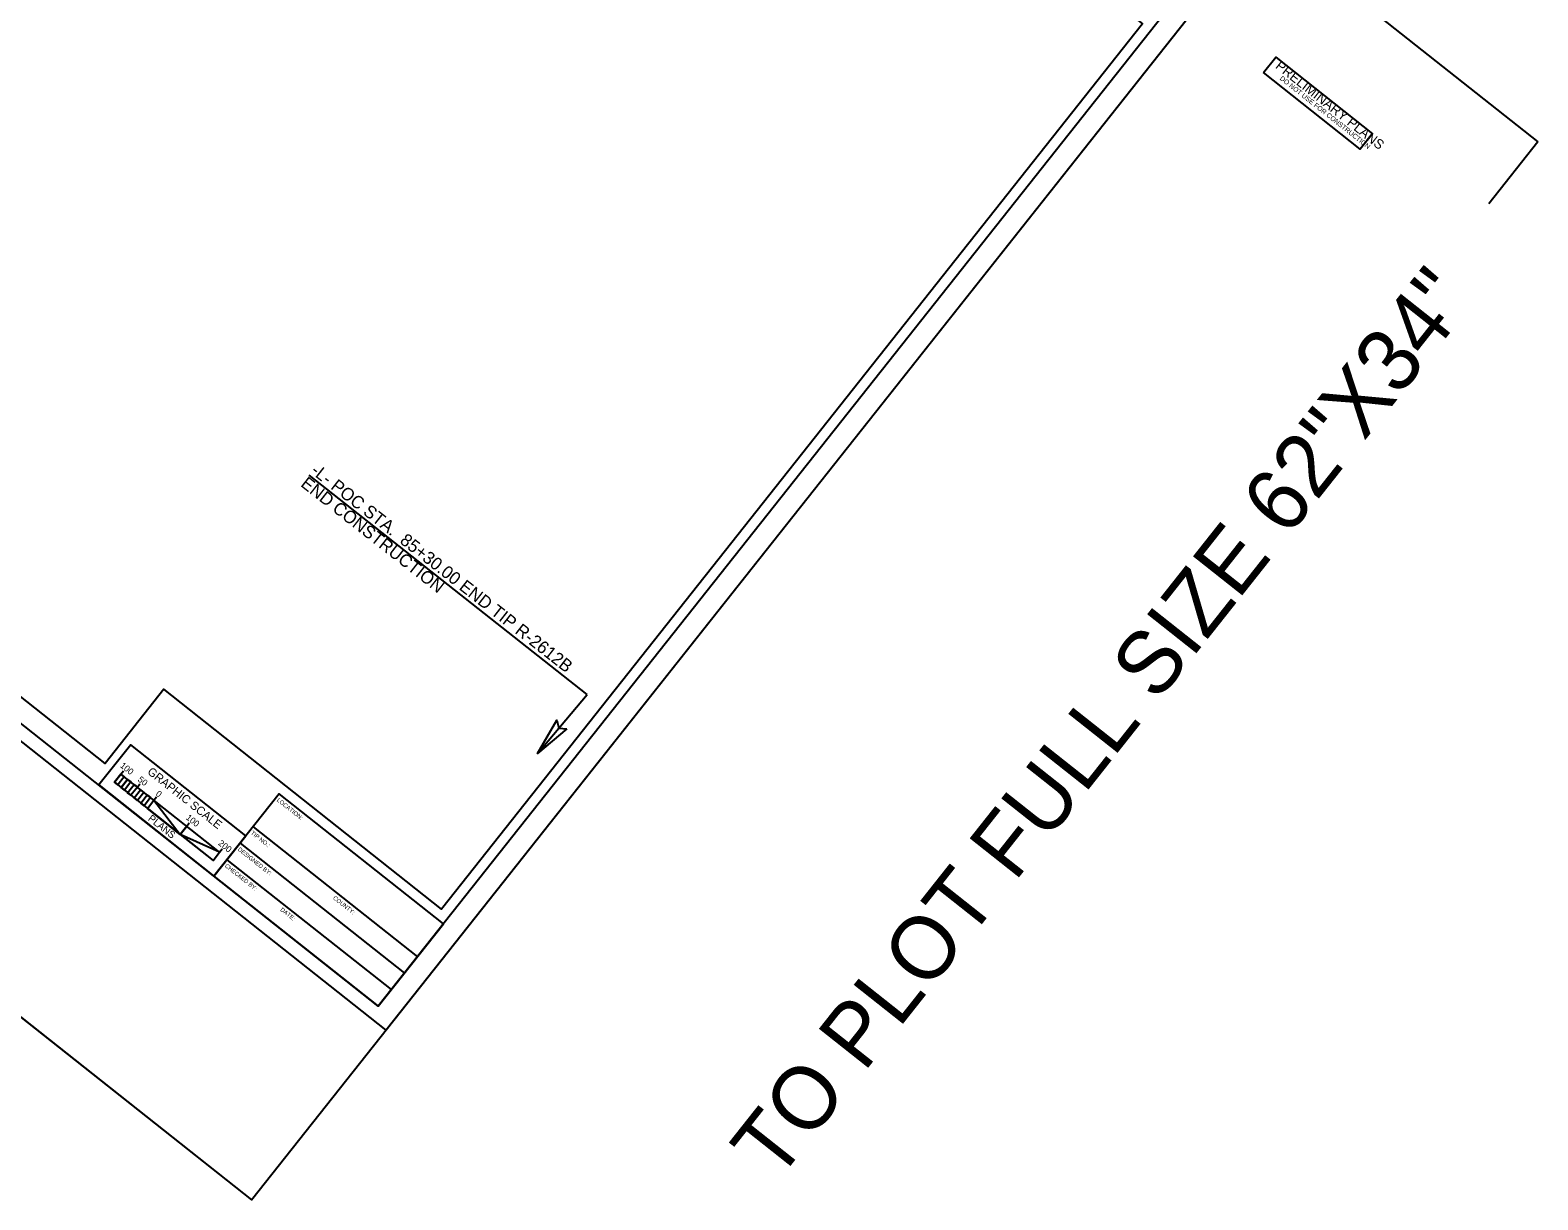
# Model space of a CAD drawing. Extents: x 1780292 to 1784627, y 810983 to 814799.
# Drawn here: x 1782828 to 1784627, y 810983 to 812379 of the extents above; entities that cross this region are included whole.
import ezdxf

# ---------------------------------------------------------------- set-up
doc = ezdxf.new("R2010")
doc.units = 0
for name, color, linetype in [('Prop Horizontal Alignment Station Label', 7, 'Continuous'), ('Prop Terminator CELL', 7, 'Continuous'), ('Sheet Clip Boundary CELL', 7, 'Continuous'), ('Sheet Cutting Line CELL', 7, 'Continuous'), ('Sheet Detail CELL', 7, 'Continuous'), ('Sheet Plot Border Inside CELL', 7, 'Continuous'), ('Sheet Plot Border Outside CELL', 7, 'Continuous'), ('Sheet Sticker Preliminary CELL', 7, 'Continuous')]:
    doc.layers.add(name, color=color, linetype=linetype)

msp = doc.modelspace()

# ---------------------------------------------------------------- linework, layer by layer
at = {"layer": 'Prop Horizontal Alignment Station Label'}
for p, q in [((1783492.6, 811586.2), (1783161, 811847.9)), ((1783433.6, 811515.7), (1783492.6, 811586.2))]:
    msp.add_line(p, q, dxfattribs=at)
at = {"layer": 'Prop Terminator CELL'}
msp.add_lwpolyline([(1783468.4, 811545.2), (1783433.6, 811515.7), (1783456.5, 811555.5), (1783458.9, 811546)], close=True, dxfattribs=at)
at = {"layer": 'Sheet Clip Boundary CELL'}
msp.add_lwpolyline([(1781927.1, 814345.3), (1784094.1, 812630.7), (1783998.7, 812510.2), (1784155.1, 812386.4), (1783319, 811330.3), (1782987.6, 811592.6), (1782917.5, 811504.1), (1780926, 813080.8)], close=True, dxfattribs=at)
at = {"layer": 'Sheet Cutting Line CELL'}
msp.add_line((1780451.8, 813073.9), (1783092.4, 810983.3), dxfattribs=at)
at = {"layer": 'Sheet Detail CELL'}
for p, q in [((1784355, 812460.7), (1784626.8, 812245.5)), ((1784626.8, 812245.5), (1784568.4, 812171.7)), ((1782936.5, 811491.2), (1782928.8, 811481.5)), ((1782936.5, 811491.2), (1782939.6, 811495.1)), ((1783054.1, 811398.1), (1782936.5, 811491.2)), ((1782940.2, 811495.9), (1782940.2, 811495.9)), ((1782928.8, 811481.5), (1783046.4, 811388.4)), ((1782944.3, 811485), (1782936.6, 811475.3)), ((1782956.1, 811475.7), (1782959.2, 811479.6)), ((1782959.8, 811480.4), (1782959.8, 811480.4)), ((1782975.7, 811460.2), (1782978.8, 811464.1)), ((1783014.9, 811429.1), (1783007.2, 811419.4)), ((1783007.2, 811419.4), (1783014.9, 811429.1)), ((1783014.9, 811429.1), (1783018, 811433.1)), ((1783018.5, 811433.9), (1783018.5, 811433.9)), ((1783094.1, 811428.4), (1783290.1, 811273.3)), ((1783054.1, 811398.1), (1783057.2, 811402)), ((1783058.1, 811402.6), (1783058.1, 811402.6)), ((1783078.6, 811408.8), (1783274.6, 811253.7)), ((1783063, 811389.2), (1783259, 811234.1))]:
    msp.add_line(p, q, dxfattribs=at)
for points in [[(1781915.6, 814370.3), (1784267.7, 812508.1), (1783243.5, 811214.5), (1780891.4, 813076.6)], [(1782910.3, 811478.3), (1783047.5, 811369.6), (1783085.6, 811417.8), (1782948.4, 811526.4)], [(1782936.5, 811491.2), (1782940.4, 811488.1), (1782932.7, 811478.4), (1782928.8, 811481.5)], [(1782944.3, 811485), (1782948.3, 811481.9), (1782940.6, 811472.2), (1782936.6, 811475.3)], [(1782952.2, 811478.8), (1782956.1, 811475.7), (1782948.4, 811466), (1782944.5, 811469.1)], [(1782960, 811472.6), (1782963.9, 811469.5), (1782956.2, 811459.8), (1782952.3, 811462.9)], [(1782967.9, 811466.4), (1782971.8, 811463.3), (1782964.1, 811453.6), (1782960.2, 811456.7)], [(1782975.7, 811460.2), (1783007.2, 811419.4), (1782968, 811450.4)], [(1783047.5, 811369.6), (1783243.5, 811214.5), (1783321.1, 811312.5), (1783125.1, 811467.6)], [(1783054.1, 811398.1), (1783007.2, 811419.4), (1783046.4, 811388.4)]]:
    msp.add_lwpolyline(points, close=True, dxfattribs=at)
at = {"layer": 'Sheet Plot Border Inside CELL'}
msp.add_lwpolyline([(1784297.9, 812505.9), (1781710.6, 814554.3), (1780665.3, 813234), (1783252.6, 811185.6)], close=True, dxfattribs=at)
at = {"layer": 'Sheet Plot Border Outside CELL'}
msp.add_lwpolyline([(1784458, 812708.2), (1781817.4, 814798.8), (1780451.8, 813073.9), (1783092.4, 810983.3)], close=True, dxfattribs=at)
at = {"layer": 'Sheet Sticker Preliminary CELL'}
msp.add_lwpolyline([(1784299.6, 812328.2), (1784314.2, 812346.6), (1784429.4, 812255.3), (1784414.9, 812236.9)], close=True, dxfattribs=at)

# ---------------------------------------------------------------- texts
at = {"layer": 'Prop Horizontal Alignment Station Label'}
for s, p in [('-L- POC STA.  85+30.00 END TIP R-2612B', (1783162, 811851)), ('END CONSTRUCTION', (1783149.9, 811835.5))]:
    msp.add_text(s, height=15, rotation=321.9257, dxfattribs=at).set_placement(p)
at = {"layer": 'Sheet Detail CELL'}
for s, height, rotation, p in [('TO PLOT FULL SIZE 62"X34"', 75, 51.6309, (1783719.1, 811003.4)), ('100', 7.5, 321.6309, (1782934.8, 811500.2)), ('GRAPHIC SCALE', 10, 321.6309, (1782967.1, 811492.5)), ('50', 7.5, 321.6309, (1782955.9, 811483.5)), ('0', 7.5, 321.6309, (1782977.3, 811466.5)), ('LOCATION:', 5, 321.6309, (1783121.9, 811459.4)), ('PLANS', 8.5, 321.6309, (1782968.1, 811436.9)), ('100', 7.5, 321.6309, (1783013.3, 811438.1)), ('TIP NO.:', 5, 321.6309, (1783090.9, 811420.2)), ('200', 7.5, 321.6309, (1783051.8, 811407.5)), ('DESIGNED BY:', 5, 321.6309, (1783075.4, 811400.6)), ('CHECKED BY:', 5, 321.6309, (1783059.9, 811381)), ('DATE:', 5, 321.6309, (1783126, 811328.7)), ('COUNTY:', 5, 321.6309, (1783188.9, 811342.7))]:
    msp.add_text(s, height=height, rotation=rotation, dxfattribs=at).set_placement(p)
at = {"layer": 'Sheet Sticker Preliminary CELL'}
for s, height, p in [('PRELIMINARY PLANS', 11.52, (1784312.9, 812334.4)), ('DO NOT USE FOR CONSTRUCTION', 5.76, (1784318.4, 812320.3))]:
    msp.add_text(s, height=height, rotation=321.6309, dxfattribs=at).set_placement(p)

doc.saveas('drawing.dxf')
